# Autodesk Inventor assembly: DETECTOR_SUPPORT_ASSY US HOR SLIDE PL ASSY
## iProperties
Shininess: 64.0
Length Units: 11272
Angle Units: 11279
Time Units: 11290
Mass Units: 11286
Length Display Precision: 3
Angle Display Precision: 2
Compacted: True
Part Number: DETECTOR_SUPPORT_ASSY US HOR SLIDE PL ASSY
Document SubType Name: Assembly
Created: 2004-08
Designer: John Blackburn
Manufacturer: Standard
Standards Organization: Custom
Density: 0.0
Volumn: 0.0
Area: 0.0
PropertySet Name: Model Information
Control State: 0
Master: False
Checked Out: False
Author: John Blackburn
